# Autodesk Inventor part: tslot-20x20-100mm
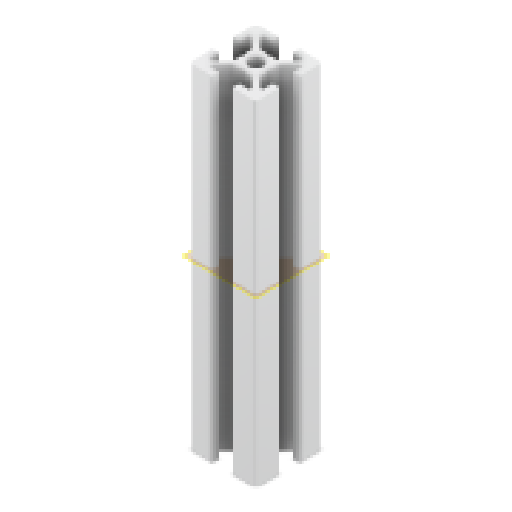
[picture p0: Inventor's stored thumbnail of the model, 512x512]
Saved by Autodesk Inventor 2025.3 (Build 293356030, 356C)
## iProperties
Created: 2025-03
Part Number: tslot-20x20-100mm
Material: Alluminio 6061
Document SubType Name: Modeling
Designer: Ryzen5700u
Density: 2.7 g/cm^3
Appearance: Alluminio - Piatto
Author: Ryzen5700u
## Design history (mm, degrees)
feature "Base1"
sketch "Schizzo1"
  geometry: L1 (3.761, -16)-(4.7, -16) reference; L2 (3.761, -16)-(0.7, -12.939) reference; L3 (0.7, -12.939)-(0.7, -10.52) reference; L4 (0.4, -10)-(0.7, -10.52) reference; L5 (0.4, -10)-(0.7, -9.48) reference; L6 (0.7, -7.061)-(0.7, -9.48) reference; L7 (3.761, -4)-(0.7, -7.061) reference; L8 (3.761, -4)-(4.7, -4) reference; L9 (4.7, -4)-(4.7, -7) reference; L10 (4.7, -7)-(6.4, -7) reference; L11 (6.7, -6.7)-(6.7, -1) reference; L12 (5.7, 0)-(0, 0) reference; L13 (-0.3, -2)-(-0.3, -0.3) reference; L14 (2.7, -2)-(-0.3, -2) reference; L15 (2.7, -2.939)-(2.7, -2) reference; L16 (2.7, -2.939)-(-0.361, -6) reference; L17 (-0.361, -6)-(-2.78, -6) reference; L18 (-3.3, -6.3)-(-2.78, -6) reference; L19 (-3.3, -6.3)-(-3.82, -6) reference; L20 (-6.239, -6)-(-3.82, -6) reference; L21 (-9.3, -2.939)-(-6.239, -6) reference; L22 (-9.3, -2.939)-(-9.3, -2) reference; L23 (-9.3, -2)-(-6.3, -2) reference; L24 (-6.3, -2)-(-6.3, -0.3) reference; L25 (-12.3, 0)-(-6.6, 0) reference; L26 (-13.3, -6.7)-(-13.3, -1) reference; L27 (-11.3, -7)-(-13, -7) reference; L28 (-11.3, -4)-(-11.3, -7) reference; L29 (-10.361, -4)-(-11.3, -4) reference; L30 (-10.361, -4)-(-7.3, -7.061) reference; L31 (-7.3, -7.061)-(-7.3, -9.48) reference; L32 (-7, -10)-(-7.3, -9.48) reference; L33 (-7, -10)-(-7.3, -10.52) reference; L34 (-7.3, -12.939)-(-7.3, -10.52) reference; L35 (-10.361, -16)-(-7.3, -12.939) reference; L36 (-10.361, -16)-(-11.3, -16) reference; L37 (-11.3, -16)-(-11.3, -13) reference; L38 (-11.3, -13)-(-13, -13) reference; L39 (-13.3, -13.3)-(-13.3, -19) reference; L40 (-12.3, -20)-(-6.6, -20) reference; L41 (-6.3, -18)-(-6.3, -19.7) reference; L42 (-9.3, -18)-(-6.3, -18) reference; L43 (-9.3, -17.061)-(-9.3, -18) reference; L44 (-9.3, -17.061)-(-6.239, -14) reference; L45 (-6.239, -14)-(-3.82, -14) reference; L46 (-3.3, -13.7)-(-3.82, -14) reference; L47 (-3.3, -13.7)-(-2.78, -14) reference; L48 (-0.361, -14)-(-2.78, -14) reference; L49 (2.7, -17.061)-(-0.361, -14) reference; L50 (2.7, -17.061)-(2.7, -18) reference; L51 (2.7, -18)-(-0.3, -18) reference; L52 (-0.3, -18)-(-0.3, -19.7) reference; L53 (5.7, -20)-(0, -20) reference; L54 (6.7, -13.3)-(6.7, -19) reference; L55 (4.7, -13)-(6.4, -13) reference; L56 (4.7, -16)-(4.7, -13) reference; C1 r 2.1 at (-3.3, -10) reference; A1 r 0.3 centre (6.4, -6.7) between (6.4, -7) and (6.7, -6.7) reference; A2 r 1 centre (5.7, -1) between (6.7, -1) and (5.7, 0) reference; A3 r 0.3 centre (0, -0.3) between (0, 0) and (-0.3, -0.3) reference; A4 r 0.3 centre (-6.6, -0.3) between (-6.3, -0.3) and (-6.6, 0) reference; A5 r 1 centre (-12.3, -1) between (-12.3, 0) and (-13.3, -1) reference; A6 r 0.3 centre (-13, -6.7) between (-13.3, -6.7) and (-13, -7) reference; A7 r 0.3 centre (-13, -13.3) between (-13, -13) and (-13.3, -13.3) reference; A8 r 1 centre (-12.3, -19) between (-13.3, -19) and (-12.3, -20) reference; A9 r 0.3 centre (-6.6, -19.7) between (-6.6, -20) and (-6.3, -19.7) reference; A10 r 0.3 centre (0, -19.7) between (-0.3, -19.7) and (0, -20) reference; A11 r 1 centre (5.7, -19) between (5.7, -20) and (6.7, -19) reference; A12 r 0.3 centre (6.4, -13.3) between (6.7, -13.3) and (6.4, -13) reference; 1 further point
extrude "Estrusione1" join sketch "Schizzo1" distance "d0" = 90; taper "d1" = 0 deg
node "Piano di lavoro1"
node "Solido1"
node "Linea chiusa proiettata1"
